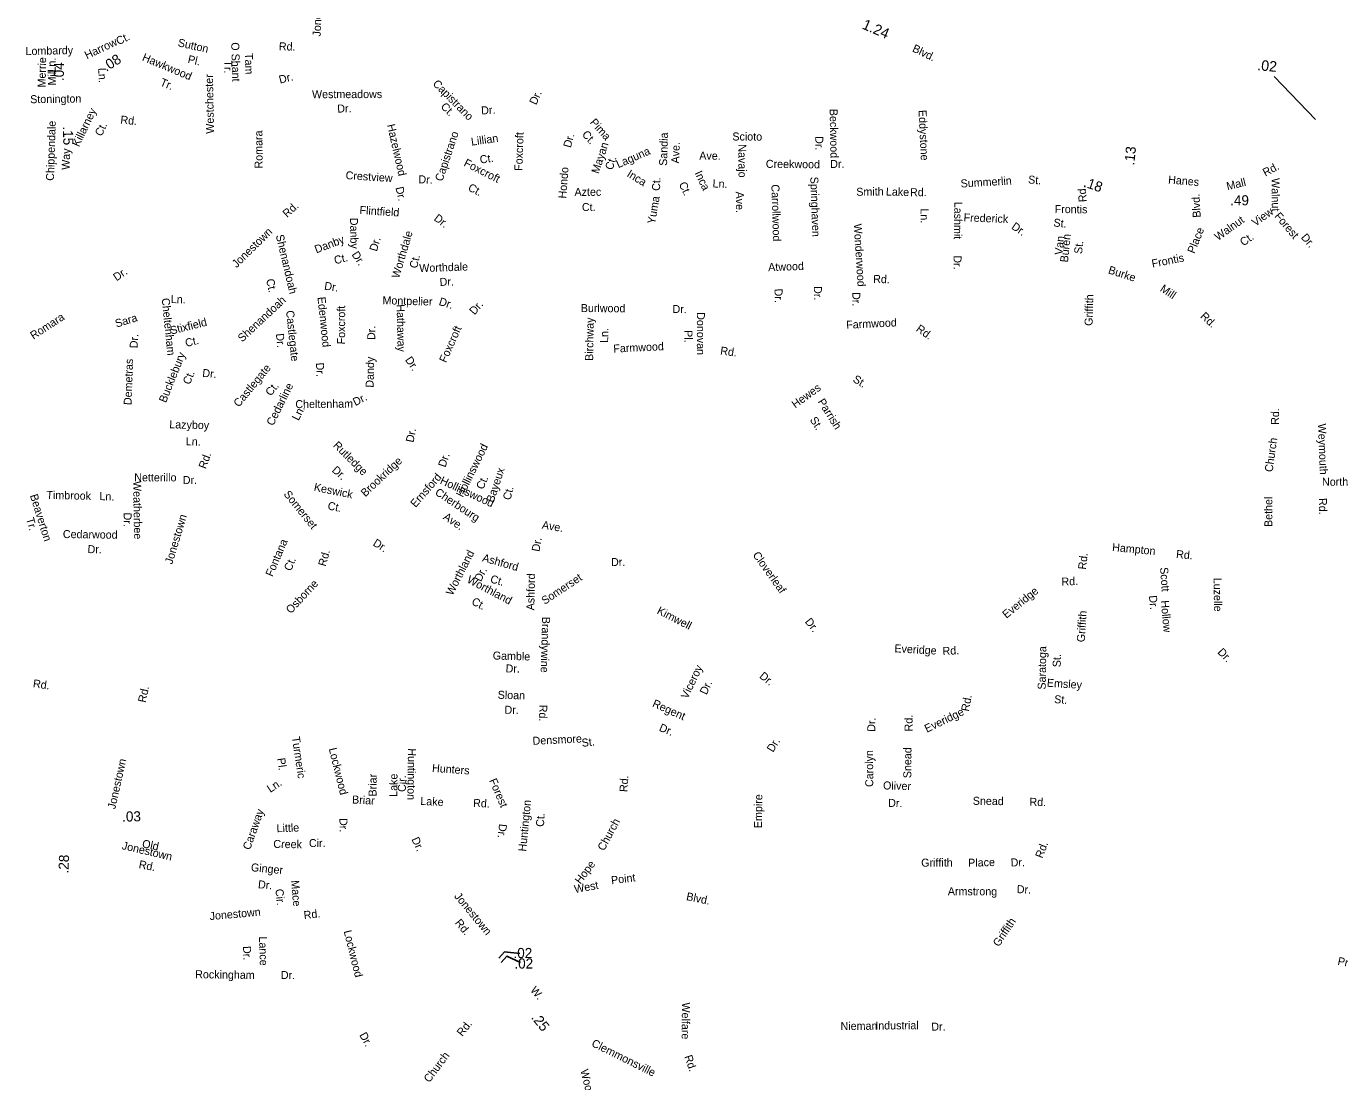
# Model space of a CAD drawing. Extents: x 1553981 to 1780076, y 812965 to 996873.
# Drawn here: x 1600309 to 1615903, y 833548 to 846079 of the extents above; entities that cross this region are included whole.
import ezdxf

# ---------------------------------------------------------------- set-up
doc = ezdxf.new("R2010")
doc.units = 0
for name, color, linetype in [('Exist Road Non-System Type 51 Label', 7, 'Continuous'), ('Exist Road Secondary Mileage Hundredths English Label', 7, 'Continuous'), ('Map Preparation Border Antique Large Shape', 7, 'Continuous')]:
    doc.layers.add(name, color=color, linetype=linetype)

msp = doc.modelspace()

# ---------------------------------------------------------------- linework, layer by layer
at = {"layer": 'Exist Road Secondary Mileage Hundredths English Label'}
msp.add_line((1615615, 844972), (1615126, 845482), dxfattribs=at)
for points in [[(1606168, 835069), (1605987, 835089), (1605918, 835015)], [(1606175, 834963), (1606014, 835040), (1605946, 834965)]]:
    msp.add_lwpolyline(points, dxfattribs=at)

# ---------------------------------------------------------------- texts
at = {"layer": 'Exist Road Non-System Type 51 Label'}
for s, rotation, p in [('Jonestown', 87.8153, (1603804, 845956)), ('Lombardy', 1.3219, (1600301, 845736)), ('Sutton', 347.5282, (1602102, 845842)), ('O Shant', 271.5619, (1602742, 845887)), ('Rd.', 358.4829, (1603307, 845794)), ('Hawkwood', 337.2498, (1601677, 845675)), ('Pl.', 347.5282, (1602220, 845645)), ('Tam', 271.6758, (1602903, 845760)), ('Ln.', 273.0229, (1601162, 845583)), ('Tr.', 268.9298, (1602661, 845675)), ('Tr.', 337.2498, (1601889, 845379)), ('Westchester', 91.1763, (1602539, 844804)), ('Dr.', 14.3562, (1603322, 845397)), ('Capistrano', 314.7034, (1605128, 845389)), ('Stonington', 0.845, (1600356, 845165)), ('Westmeadows', 0.0773, (1603701, 845225)), ('Dr.', 65.0758, (1606362, 845138)), ('Killarney', 64.2903, (1600934, 844640)), ('Dr.', 0.9437, (1604002, 845054)), ('Ct.', 314.7034, (1605222, 845118)), ('Dr.', 3.4505, (1605712, 845031)), ('Beckwood', 270.9893, (1609847, 845098)), ('Eddystone', 272.759, (1610902, 845083)), ('Ct.', 64.2903, (1601203, 844765)), ('Rd.', 354.0482, (1601423, 844925)), ('Hazelwood', 282.711, (1604592, 844907)), ('Pima', 311.5089, (1606995, 844933)), ('Romara', 90.344, (1603115, 844390)), ('Capistrano', 71.3687, (1605248, 844230)), ('Lillian', 8.0194, (1605596, 844661)), ('Foxcroft', 88.0167, (1606198, 844361)), ('Dr.', 74.5948, (1606773, 844630)), ('Ct.', 311.5089, (1606900, 844791)), ('Sandia', 88.2415, (1607916, 844421)), ('Scioto', 359.7202, (1608692, 844723)), ('Dr.', 270.9893, (1609676, 844774)), ('Mayan', 71.9936, (1607105, 844321)), ('Laguna', 23.7138, (1607338, 844393)), ('Ave.', 88.2415, (1608060, 844449)), ('Ave.', 359.7809, (1608299, 844495)), ('Navajo', 270.4883, (1608762, 844677)), ('Foxcroft', 332.9533, (1605495, 844426)), ('Ct.', 8.0194, (1605700, 844448)), ('Ct.', 71.9936, (1607268, 844365)), ('Creekwood', 359.4596, (1609089, 844398)), ('Dr.', 0.9066, (1609854, 844396)), ('Crestview', 356.3818, (1604098, 844264)), ('Dr.', 357.8835, (1604963, 844215)), ('Hondo', 85.7365, (1606719, 844031)), ('Inca', 328.7243, (1607431, 844301)), ('Ct.', 87.5823, (1607832, 844123)), ('Inca', 295.3397, (1608242, 844337)), ('Springhaven', 271.9675, (1609617, 844291)), ('Summerlin', 3.4679, (1611405, 844164)), ('St.', 354.8615, (1612200, 844214)), ('Walnut', 270.5797, (1615093, 844276)), ('Dr.', 282.711, (1604692, 844163)), ('Ct.', 332.9533, (1605545, 844134)), ('Aztec', 0.1653, (1606818, 844065)), ('Ct.', 295.3397, (1608054, 844205)), ('Ln.', 357.6071, (1608456, 844166)), ('Ave.', 270.4883, (1608733, 844116)), ('Carrollwood', 271.6696, (1609155, 844201)), ('Smith', 0.7496, (1610164, 844066)), ('Lake', 358.3743, (1610514, 844070)), ('Rd.', 0.2546, (1610801, 844061)), ('Rd.', 94.0375, (1612899, 843994)), ('Rd.', 42.2222, (1603405, 843802)), ('Ct.', 0.1653, (1606906, 843885)), ('Yuma', 80.3075, (1607774, 843726)), ('Lashmit', 268.9633, (1611329, 843996)), ('Frontis', 359.3732, (1612518, 843862)), ('Blvd.', 93.3677, (1614254, 843809)), ('Flintfield', 356.2379, (1604263, 843851)), ('Dr.', 322.5031, (1605141, 843783)), ('Ln.', 270.3062, (1610926, 843917)), ('Frederick', 357.9779, (1611436, 843762)), ('Walnut', 35.5025, (1614458, 843528)), ('View', 35.5025, (1614901, 843698)), ('Forest', 310.2822, (1615122, 843821)), ('Jonestown', 44.5593, (1602806, 843205)), ('Danby', 270.9403, (1604152, 843804)), ('Worthdale', 73.6511, (1604735, 843079)), ('Wonderwood', 273.5466, (1610133, 843732)), ('Dr.', 325.3842, (1611997, 843681)), ('St.', 353.8856, (1612501, 843703)), ('Place', 68.1429, (1614178, 843373)), ('Shenandoah', 283.244, (1603271, 843595)), ('Danby', 20.9696, (1603753, 843381)), ('Dr.', 73.1942, (1604470, 843399)), ('Van', 84.335, (1612611, 843360)), ('Buren', 84.2065, (1612676, 843272)), ('St.', 84.087, (1612843, 843372)), ('Ct.', 35.5025, (1614760, 843464)), ('Dr.', 310.2822, (1615437, 843569)), ('Ct.', 14.2592, (1603976, 843252)), ('Dr.', 303.1614, (1604168, 843369)), ('Ct.', 76.5891, (1604948, 843198)), ('Dr.', 270.2185, (1611318, 843359)), ('Frontis', 11.1772, (1613680, 843213)), ('Dr.', 34.5219, (1601381, 843049)), ('Worthdale', 1.8783, (1604976, 843160)), ('Atwood', 2.0432, (1609119, 843171)), ('Burke', 342.0226, (1613147, 843147)), ('Ct.', 282.0873, (1603156, 843071)), ('Dr.', 351.3708, (1603842, 842953)), ('Dr.', 1.8783, (1605218, 842996)), ('Rd.', 358.4539, (1610363, 843032)), ('Ln.', 358.3621, (1602024, 842793)), ('Montpelier', 358.3972, (1604537, 842779)), ('Dr.', 271.5713, (1609192, 842963)), ('Dr.', 270.4972, (1609660, 842994)), ('Dr.', 270.6902, (1610116, 842923)), ('Griffith', 88.4852, (1612968, 842521)), ('Mill', 326.2885, (1613762, 842941)), ('Cheltenham', 275.8255, (1601916, 842848)), ('Shenandoah', 43.0276, (1602873, 842324)), ('Edenwood', 275.8607, (1603766, 842862)), ('Foxcroft', 89.8531, (1604094, 842302)), ('Hathaway', 271.2288, (1604706, 842777)), ('Dr.', 342.2535, (1605200, 842772)), ('Dr.', 49.3023, (1605631, 842645)), ('Burlwood', 359.6562, (1606892, 842686)), ('Dr.', 359.1067, (1607981, 842675)), ('Romara', 33.1085, (1600394, 842357)), ('Sara', 16.9816, (1601380, 842501)), ('Stixfield', 14.0653, (1602030, 842418)), ('Castlegate', 275.8812, (1603393, 842701)), ('Birchway', 89.1732, (1607039, 842105)), ('Donovan', 270.0052, (1608271, 842684)), ('Farmwood', 2.769, (1610046, 842487)), ('Rd.', 316.8411, (1614241, 842627)), ('Dr.', 87.0268, (1601630, 842254)), ('Dr.', 275.8812, (1603272, 842428)), ('Dr.', 89.8644, (1604452, 842354)), ('Foxcroft', 66.001, (1605293, 842077)), ('Ln.', 88.401, (1607216, 842318)), ('Pl.', 270.0052, (1608123, 842471)), ('Rd.', 324.3512, (1610865, 842468)), ('Ct.', 14.0653, (1602208, 842270)), ('Farmwood', 2.769, (1607281, 842204)), ('Rd.', 352.2663, (1608544, 842183)), ('Demetras', 88.1229, (1601559, 841580)), ('Bucklebury', 68.0896, (1601967, 841602)), ('Dandy', 88.6743, (1604432, 841787)), ('Dr.', 304.3133, (1604802, 842118)), ('Ct.', 68.0896, (1602251, 841817)), ('Dr.', 354.6518, (1602396, 841917)), ('Castlegate', 50.4695, (1602833, 841550)), ('Dr.', 272.1161, (1603748, 842084)), ('St.', 328.0849, (1610114, 841865)), ('Ct.', 50.4695, (1603211, 841681)), ('Cedarline', 63.515, (1603240, 841328)), ('Hewes', 36.1072, (1609439, 841539)), ('Cheltenham', 0.4957, (1603504, 841545)), ('Dr.', 27.4567, (1604216, 841568)), ('Parrish', 302.2183, (1609701, 841622)), ('Ln.', 63.515, (1603542, 841390)), ('Rd.', 89.1397, (1615181, 841346)), ('Lazyboy', 358.5766, (1602006, 841306)), ('St.', 302.2183, (1609608, 841407)), ('Weymouth', 272.2008, (1615644, 841360)), ('Ln.', 358.5766, (1602202, 841104)), ('Rutledge', 315.1222, (1603945, 841096)), ('Dr.', 78.6944, (1604906, 841132)), ('Church', 81.9559, (1615105, 840782)), ('Rd.', 69.9179, (1602440, 840817)), ('Hollinswood', 63.7592, (1605492, 840479)), ('Dr.', 317.8643, (1603930, 840798)), ('Brookridge', 43.4235, (1604334, 840486)), ('Dr.', 71.5029, (1605285, 840836)), ('Bayeux', 71.7464, (1605857, 840418)), ('Netterillo', 359.8758, (1601591, 840676)), ('Dr.', 359.8758, (1602167, 840644)), ('Ernsford', 48.9478, (1604931, 840359)), ('Hollinswood', 335.1944, (1605213, 840652)), ('Ct.', 65.483, (1605731, 840571)), ('Northridge', 0.37, (1615693, 840623)), ('Beaverton', 287.3595, (1600351, 840508)), ('Timbrook', 358.6499, (1600547, 840468)), ('Ln.', 357.8249, (1601176, 840454)), ('Weatherbee', 270.8569, (1601578, 840679)), ('Somerset', 308.9869, (1603359, 840521)), ('Keswick', 348.2657, (1603718, 840566)), ('Cherbourg', 326.4543, (1605153, 840524)), ('Ct.', 75.9447, (1606057, 840447)), ('Ct.', 348.2657, (1603881, 840344)), ('Bethel', 90.0963, (1615103, 840134)), ('Rd.', 270.6614, (1615656, 840478)), ('Tr.', 285.4394, (1600306, 840232)), ('Dr.', 269.7218, (1601465, 840305)), ('Jonestown', 73.267, (1602042, 839686)), ('Ave.', 326.4543, (1605250, 840233)), ('Cedarwood', 359.2474, (1600743, 840003)), ('Ave.', 350.3393, (1606426, 840116)), ('Dr.', 358.7892, (1601036, 839824)), ('Fontana', 67.0352, (1603232, 839537)), ('Dr.', 327.9296, (1604416, 839920)), ('Dr.', 79.5981, (1606400, 839836)), ('Hampton', 354.6087, (1613198, 839849)), ('Ct.', 67.0352, (1603451, 839603)), ('Rd.', 74.2085, (1603863, 839660)), ('Worthland', 62.9123, (1605369, 839313)), ('Ashford', 344.2213, (1605716, 839728)), ('Dr.', 0.7751, (1607252, 839670)), ('Cloverleaf', 305.5232, (1608928, 839801)), ('Rd.', 83.6073, (1612890, 839625)), ('Rd.', 354.4318, (1613957, 839767)), ('Dr.', 62.9123, (1605706, 839477)), ('Scott', 273.9873, (1613770, 839654)), ('Osborne', 47.1387, (1603451, 839098)), ('Worthland', 332.2038, (1605532, 839480)), ('Ct.', 344.2213, (1605810, 839477)), ('Ashford', 88.7134, (1606340, 839144)), ('Somerset', 33.7089, (1606465, 839209)), ('Rd.', 2.5925, (1612601, 839437)), ('Luzelle', 270.8853, (1614405, 839531)), ('Ct.', 332.2038, (1605587, 839221)), ('Everidge', 39.0892, (1611945, 839043)), ('Dr.', 275.7066, (1613637, 839318)), ('Kimwell', 333.1312, (1607788, 839110)), ('Griffith', 86.3415, (1612875, 838764)), ('Hollow', 275.0661, (1613779, 839259)), ('Brandywine', 268.4557, (1606434, 839069)), ('Dr.', 308.1253, (1609548, 839008)), ('Gamble', 358.4396, (1605846, 838561)), ('Everidge', 356.8202, (1610614, 838647)), ('Rd.', 2.5925, (1611189, 838614)), ('Saratoga', 88.9626, (1612411, 838203)), ('Dr.', 314.1351, (1614446, 838642)), ('Dr.', 358.4396, (1605999, 838408)), ('Viceroy', 64.7398, (1608161, 838085)), ('St.', 88.9626, (1612590, 838469)), ('Dr.', 320.8314, (1609005, 838350)), ('Rd.', 77.8454, (1601726, 838043)), ('Sloan', 358.5708, (1605905, 838095)), ('Dr.', 64.7398, (1608385, 838135)), ('Emsley', 356.4002, (1612424, 838238)), ('Regent', 335.9004, (1607734, 838005)), ('Rd.', 79.5973, (1611500, 837939)), ('St.', 356.4002, (1612511, 838043)), ('Dr.', 358.5708, (1605986, 837917)), ('Rd.', 268.9474, (1606400, 838024)), ('Rd.', 90.3092, (1610832, 837707)), ('Everidge', 25.7948, (1611001, 837690)), ('Dr.', 337.6899, (1607814, 837717)), ('Dr.', 87.975, (1610387, 837701)), ('Turmeric', 278.3725, (1603462, 837640)), ('Densmore', 2.8385, (1606322, 837547)), ('St.', 6.692, (1606908, 837523)), ('Dr.', 57.8064, (1609174, 837452)), ('Lockwood', 283.8709, (1603900, 837501)), ('Huntington', 269.3156, (1604841, 837507)), ('Carolyn', 90.3125, (1610365, 837047)), ('Snead', 89.6017, (1610816, 837151)), ('Jonestown', 77.3766, (1601365, 836779)), ('Pl.', 278.3725, (1603288, 837386)), ('Hunters', 355.6771, (1605124, 837228)), ('Ln.', 33.6855, (1603206, 836976)), ('Briar', 89.4479, (1604467, 836934)), ('Lake', 89.4479, (1604714, 836930)), ('Cir.', 89.4479, (1604815, 836988)), ('Forest', 293.2123, (1605802, 837125)), ('Rd.', 86.5199, (1607446, 836985)), ('Oliver', 358.4221, (1610480, 837019)), ('Briar', 356.9657, (1604175, 836852)), ('Empire', 89.2308, (1609043, 836558)), ('Caraway', 70.4608, (1602965, 836293)), ('Lake', 356.9657, (1604986, 836835)), ('Rd.', 356.9657, (1605612, 836812)), ('Huntington', 84.4163, (1606243, 836278)), ('Dr.', 358.4221, (1610540, 836812)), ('Snead', 359.2662, (1611546, 836836)), ('Rd.', 358.7317, (1612219, 836824)), ('Dr.', 270.9439, (1604027, 836678)), ('Ct.', 86.3946, (1606454, 836572)), ('Church', 61.8096, (1607169, 836281)), ('Little', 1.9736, (1603282, 836510)), ('Dr.', 263.7691, (1605923, 836613)), ('Jonestown', 346.8914, (1601438, 836310)), ('Old', 348.5677, (1601678, 836332)), ('Creek', 359.2404, (1603242, 836324)), ('Cir.', 0.0327, (1603665, 836334)), ('Dr.', 294.4468, (1604880, 836427)), ('Rd.', 69.2552, (1612373, 836194)), ('Rd.', 348.6543, (1601639, 836086)), ('Hope', 53.2277, (1606889, 835887)), ('Griffith', 0.3257, (1610934, 836101)), ('Place', 1.8353, (1611493, 836099)), ('Dr.', 1.1085, (1611997, 836103)), ('Ginger', 354.6976, (1602973, 836048)), ('Point', 7.0056, (1607258, 835892)), ('Dr.', 354.6976, (1603057, 835846)), ('Mace', 274.5595, (1603453, 835936)), ('West', 10.0963, (1606823, 835787)), ('Armstrong', 359.8531, (1611250, 835762)), ('Dr.', 357.1992, (1612067, 835788)), ('Cir.', 275.8632, (1603266, 835833)), ('Jonestown', 309.4999, (1605384, 835747)), ('Blvd.', 348.2201, (1608139, 835706)), ('Jonestown', 5.0383, (1602490, 835466)), ('Rd.', 6.7567, (1603608, 835477)), ('Rd.', 309.4999, (1605393, 835432)), ('Griffith', 56.1906, (1611856, 835143)), ('Lance', 271.7885, (1603072, 835271)), ('Lockwood', 283.8709, (1604077, 835335)), ('Dr.', 271.7885, (1602882, 835158)), ('Primrose', 348.1269, (1615872, 834938)), ('Rockingham', 359.2355, (1602314, 834777)), ('Dr.', 359.2322, (1603331, 834768)), ('Welfare', 269.6789, (1608093, 834489)), ('Dr.', 298.6802, (1604260, 834103)), ('Nieman', 0.5895, (1609977, 834161)), ('Industrial', 0.4757, (1610389, 834167)), ('Dr.', 0.2857, (1611054, 834154)), ('Rd.', 288.919, (1608120, 833847))]:
    msp.add_text(s, height=95, rotation=rotation, dxfattribs=at).set_placement(p)
at = {"layer": 'Exist Road Secondary Mileage Hundredths English Label'}
for s, height, rotation, p in [('1.24', 125, 336.6928, (1610223, 846054)), ('.08', 120, 32.319, (1601260, 845537)), ('.02', 125, 354.6678, (1614920, 845558)), ('.04', 120, 88.7922, (1600754, 845427)), ('.15', 120, 271.6656, (1600743, 844888)), ('.13', 120, 84.1982, (1613463, 844425)), ('.18', 120, 341.1859, (1612851, 844178)), ('.03', 120, 1.0233, (1601448, 836636)), ('.28', 120, 87.5736, (1600809, 836018)), ('.25', 120, 308.5638, (1606297, 834308))]:
    msp.add_text(s, height=height, rotation=rotation, dxfattribs=at).set_placement(p)
for s, p in [('.49', (1614602, 843953)), ('.02', (1606093, 835016)), ('.02', (1606104, 834892))]:
    msp.add_text(s, height=120, dxfattribs=at).set_placement(p)
at = {"layer": 'Map Preparation Border Antique Large Shape'}
for s, rotation, p in [('Harrow', 25.3296, (1601029, 845686)), ('Ct.', 25.3296, (1601402, 845853)), ('Blvd.', 334.0784, (1610820, 845784)), ('Merrie', 88.9199, (1600538, 845351)), ('Ln.', 88.9199, (1600656, 845528)), ('Mill', 88.9199, (1600661, 845375)), ('Chippendale', 88.2008, (1600637, 844243)), ('Way', 88.2008, (1600823, 844373)), ('Rd.', 28.1406, (1615020, 844293)), ('Hanes', 355.0862, (1613863, 844213)), ('Mall', 13.3493, (1614570, 844132)), ('Rd.', 351.9275, (1600384, 838232)), ('W.', 309.69, (1606287, 834632)), ('Rd.', 51.3813, (1605485, 834079)), ('Clemmonsville', 333.5575, (1607011, 833974)), ('Church', 53.2758, (1605095, 833530)), ('Woodward', 283.9357, (1606887, 833683))]:
    msp.add_text(s, height=95, rotation=rotation, dxfattribs=at).set_placement(p)

doc.saveas('drawing.dxf')
